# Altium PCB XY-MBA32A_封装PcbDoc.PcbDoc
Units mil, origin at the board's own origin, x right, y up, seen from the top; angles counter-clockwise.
Board outline 6000 x 4000 mil, 3 copper layers (Top Layer, Mid-Layer 1, Bottom Layer); 1 components, 0 nets, 18 pads, 0 vias.
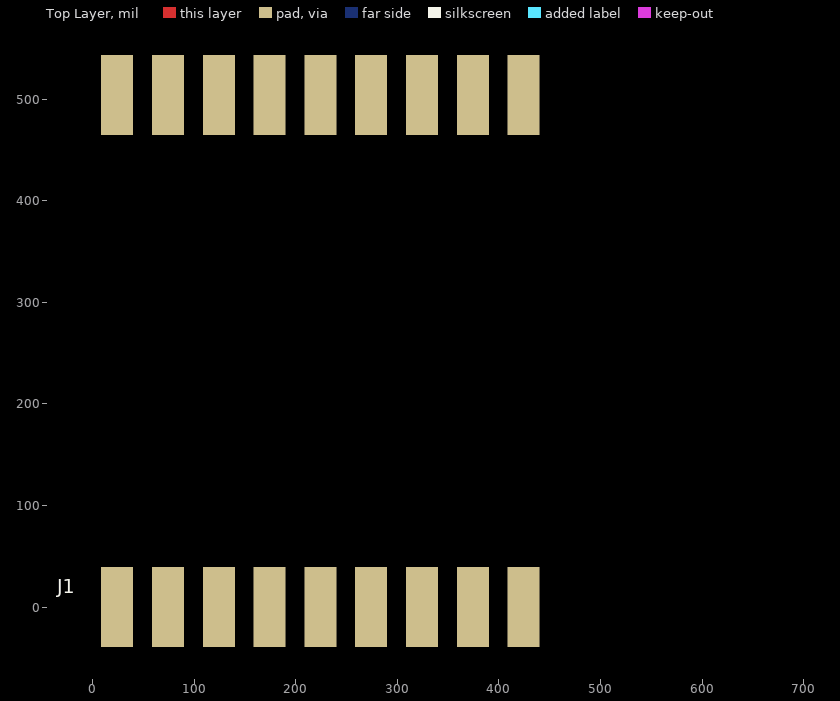
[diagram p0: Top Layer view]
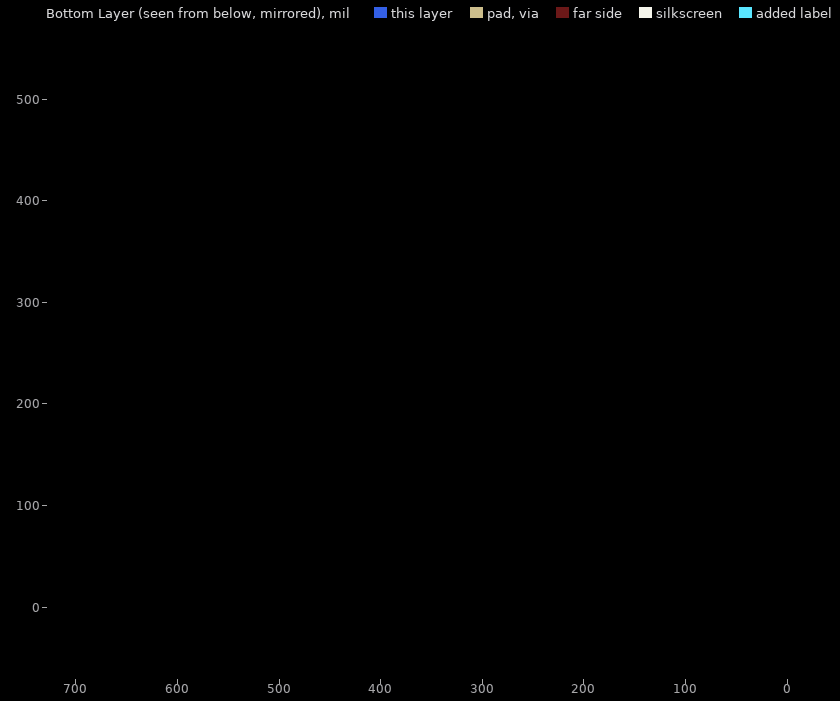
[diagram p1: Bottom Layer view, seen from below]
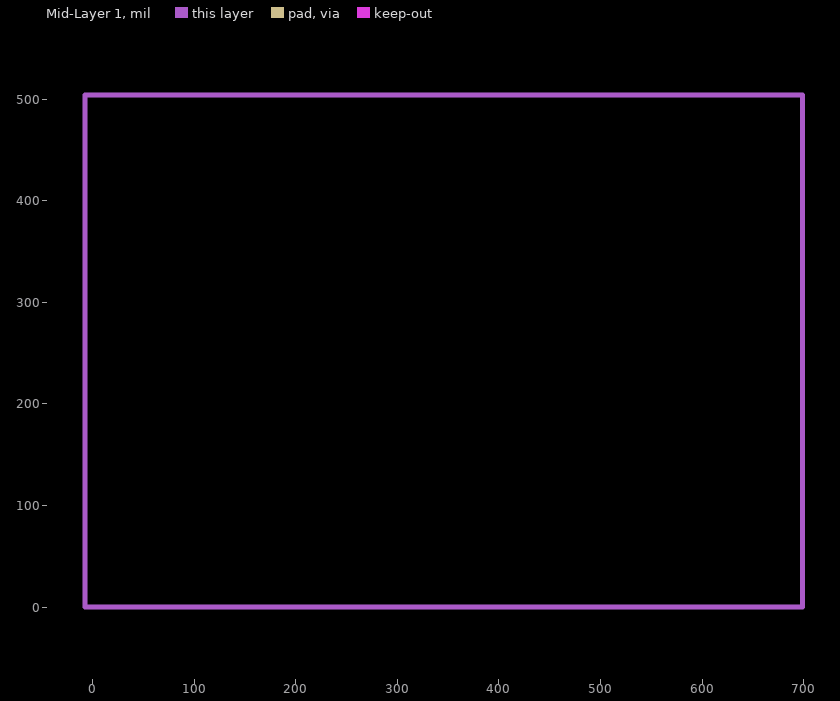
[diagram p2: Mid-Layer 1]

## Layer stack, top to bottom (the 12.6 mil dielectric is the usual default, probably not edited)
Top Solder: solder mask 0.4, Solder Resist, Dk 3.5
Top Layer: signal copper 1.4
Dielectric 1: dielectric 12.6, FR-4, Dk 4.8
Mid-Layer 1: signal copper 1.4
Dielectric2: dielectric 12.6, FR-4, Dk 4.8
Bottom Layer: signal copper 1.4
Bottom Solder: solder mask 0.4, Solder Resist, Dk 3.5

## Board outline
-9543.64,-9340.58 -3543.64,-9340.58 -3543.64,-5340.58 -9543.64,-5340.58

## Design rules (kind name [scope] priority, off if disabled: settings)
Clearance [All] p1: gap=10
FanoutControl Fanout_LCC [IsLCC] p1: bgadir=Out bgaviamode=Centered fanoutstyle=Auto fanoutdirection=Alternating viagrid=1 // Fanout_LCC (Default Rule)
FanoutControl Fanout_BGA [IsBGA] p2: bgadir=Out bgaviamode=Centered fanoutstyle=Auto fanoutdirection=Alternating viagrid=1 // Fanout_BGA (Default Rule)
FanoutControl Fanout_Small [(CompPinCount < 5)] p3: bgadir=Out bgaviamode=Centered fanoutstyle=Auto fanoutdirection=OutThenIn viagrid=1 // Fanout_Small (Default Rule)
FanoutControl Fanout_SOIC [IsSOIC] p4: bgadir=Out bgaviamode=Centered fanoutstyle=Auto fanoutdirection=Alternating viagrid=1 // Fanout_SOIC (Default Rule)
PolygonConnect [All] p1: connectstyle=Relief reliefconductorwidth=10 reliefentries=4 polygonreliefangle="90 Angle" airgapwidth=10
RoutingVias [All] p1: holewidth=28 width=50 viastyle="Through Hole" minholewidth=28 minwidth=50 maxholewidth=28 maxwidth=50
SolderMaskExpansion [All] p1: expansion=4
Width [All] p1: maxlimit=10 minlimit=10 preferedwidth=10
26 further rules are at their usual default settings.

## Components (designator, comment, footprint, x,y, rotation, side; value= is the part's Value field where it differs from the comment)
J1 "6621_32A" 6621_32A -7.24,0 r0 top

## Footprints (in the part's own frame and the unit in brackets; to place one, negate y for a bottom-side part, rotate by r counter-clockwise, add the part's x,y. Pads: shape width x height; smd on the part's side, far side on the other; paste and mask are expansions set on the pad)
6621_32A [mm]
  rect 0.8x2 smd: 1(10.96,12.8) 2(9.69,12.8) 3(8.42,12.8) 4(7.15,12.8) 5(5.88,12.8) 6(4.61,12.8) 7(3.34,12.8) 8(2.07,12.8) 9(0.8,12.8) 10(0.8,0) 11(2.07,0) 12(3.34,0) 13(4.61,0) 14(5.88,0) 15(7.15,0) 16(8.42,0) 17(9.69,0) 18(10.96,0)
  Mid-Layer 1 lines w0.127: 0,0 17.93,0 17.93,12.8 0,12.8 0,0

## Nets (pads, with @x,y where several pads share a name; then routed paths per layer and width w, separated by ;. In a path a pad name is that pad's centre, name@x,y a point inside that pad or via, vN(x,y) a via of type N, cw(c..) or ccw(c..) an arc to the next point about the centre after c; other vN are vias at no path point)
pads on no net: J1.1 J1.2 J1.3 J1.4 J1.5 J1.6 J1.7 J1.8 J1.9 J1.10 J1.11 J1.12 J1.13 J1.14 J1.15 J1.16 J1.17 J1.18

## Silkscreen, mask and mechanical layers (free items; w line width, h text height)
Mechanical 15:
  text "XY-MBA32A" at 536.73,325.09 h29.53 r270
